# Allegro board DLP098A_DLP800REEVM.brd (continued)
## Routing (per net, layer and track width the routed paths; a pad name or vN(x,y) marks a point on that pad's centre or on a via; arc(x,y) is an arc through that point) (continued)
S_DDA13_P: length 124.5
  TOP w0.191: U8.C16 v1(37.31,41.12)
  03_SIG1 w0.108: v1(37.31,41.12) 37.71,41.12 37.82,41.23 37.82,45.8 36.61,47.01 30.27,47.01 29.98,47.3 29.98,49.21 30.71,49.94 30.71,54.1 31.44,54.83 32.69,54.83 33.8,53.72 38.71,53.72 38.98,53.46 38.98,52.82 38.72,52.57 34.37,52.57 33.05,51.25 33.05,49.16 33.2,49 34.6,49 34.92,49.32 41.79,49.32 42.94,50.47 42.94,54.51 41.63,55.83 41.63,62.71 41.9,62.98 42.54,62.98 42.82,62.7 42.82,58.15 43.61,57.35 46.89,57.35 47.51,57.97 47.51,61.91 48.53,62.94 50.16,62.94 53.12,65.9 53.12,67.19 54.78,68.84 54.78,74.82 55.16,75.2 74.84,75.2 75.1,75.46 75.1,80.05 73.83,81.32 73.83,81.95 73.72,82.06 v1(73.32,82.06)
  BOTTOM w0.108: J500.D17 v1(73.32,82.06)
S_DDA14_N: length 124.4
  TOP w0.191: U8.B15 v1(36.04,42.39)
  05_SIG2 w0.108: v1(75.86,83.33) 75.7,83.17 75.46,83.17 75.24,83.38 75.24,83.63 75.46,83.84 76.23,83.84 76.37,83.7 76.37,68.33 74.71,66.67 73.89,66.67 73.58,66.98 73.58,67.32 74.27,68.01 74.27,68.81 73.81,69.27 73.05,69.27 71.79,68.01 71.79,66.12 67.22,61.56 66.94,61.56 66.66,61.83 66.66,62.19 69.52,65.05 69.52,65.72 69.06,66.18 68.46,66.18 64.91,62.63 64.91,61.63 67.17,59.37 67.17,59.02 66.96,58.81 66.38,58.81 64.13,61.06 63.77,61.06 63.37,60.66 63.37,60.09 65.52,57.94 65.52,57.61 65.24,57.33 64.96,57.33 61.85,60.44 53.99,60.44 51.23,57.68 51.23,57.21 51.73,56.71 52.4,56.71 54.88,59.18 55.34,59.18 55.62,58.91 55.62,58.66 51.25,54.29 49.69,54.29 48.46,53.06 48.46,52.59 47.13,51.25 44.13,51.25 43.79,50.92 39.8,50.92 39.5,50.62 39.5,50.06 39.81,49.75 43.48,49.75 43.63,49.59 43.63,49.31 43.43,49.11 39.7,49.11 39.36,48.78 39.36,47.6 39.92,47.04 39.92,46.25 39.65,45.99 37.84,45.99 36.55,44.71 36.55,42.47 36.45,42.36 36.08,42.36 v1(36.04,42.39)
  BOTTOM w0.108: J500.C19 v1(75.86,83.33)
S_DDA14_P: length 124.5
  TOP w0.191: U8.B16 v1(37.31,42.39)
  05_SIG2 w0.108: v1(74.59,83.33) 75.35,84.09 76.34,84.09 76.62,83.81 76.62,68.22 74.82,66.42 73.78,66.42 73.32,66.87 73.32,67.42 74.02,68.12 74.02,68.7 73.71,69.01 73.15,69.01 72.04,67.91 72.04,66.02 67.33,61.3 66.84,61.3 66.41,61.73 66.41,62.3 69.27,65.15 69.27,65.61 68.95,65.93 68.57,65.93 65.16,62.52 65.16,61.73 67.42,59.47 67.42,58.92 67.06,58.56 66.28,58.56 64.03,60.81 63.87,60.81 63.62,60.56 63.62,60.2 65.77,58.05 65.77,57.51 65.35,57.08 64.85,57.08 61.74,60.19 54.09,60.19 51.48,57.58 51.48,57.32 51.84,56.96 52.3,56.96 54.78,59.44 55.45,59.44 55.87,59.02 55.87,58.55 51.35,54.04 49.8,54.04 48.72,52.96 48.72,52.48 47.23,51 44.23,51 43.9,50.66 39.9,50.66 39.76,50.51 39.76,50.16 39.91,50 43.58,50 43.89,49.7 43.89,49.21 43.53,48.85 39.8,48.85 39.62,48.67 39.62,47.7 40.17,47.15 40.17,46.15 39.76,45.74 37.94,45.74 36.81,44.6 36.81,42.9 v1(37.31,42.39)
  BOTTOM w0.108: J500.C18 v1(74.59,83.33)
S_DDA15_N: length 124.5
  TOP w0.191: U8.D15 v1(36.04,39.85)
  03_SIG1 w0.108: v1(36.04,39.85) 36.04,39.45 35.94,39.34 35.78,39.34 35.55,39.58 35.55,40.25 35.66,40.36 39.04,40.36 39.35,40.67 39.35,44.48 39.54,44.67 41.82,44.67 42.19,45.05 42.19,45.93 41.82,46.31 38.91,46.31 38.75,46.48 38.75,47.06 38.96,47.27 42.67,47.27 43.21,47.81 43.21,48.75 44.82,50.37 44.82,52.87 48.67,56.71 48.67,59.67 54.33,65.33 54.33,66.77 55.19,67.63 55.5,67.63 55.72,67.42 55.72,67.15 55.26,66.69 55.26,64.97 49.45,59.17 49.45,56.41 45.61,52.57 45.61,49.46 45.98,49.08 46.93,49.08 47.4,49.55 47.4,52.62 50.62,55.85 50.62,58.32 57.22,64.91 57.22,67.89 56.3,68.81 56.3,73.38 56.6,73.68 75.42,73.68 76.47,74.74 76.47,75.57 76.62,75.71 v1(77.13,75.71)
  BOTTOM w0.108: J500.H20 v1(77.13,75.71)
S_DDA15_P: length 124.5
  TOP w0.191: U8.E15 v1(36.04,38.58)
  03_SIG1 w0.108: v1(75.86,75.71) 76.22,75.35 76.22,74.84 75.31,73.93 56.49,73.93 56.05,73.49 56.05,68.7 56.96,67.79 56.96,65.02 50.37,58.43 50.37,55.95 47.14,52.72 47.14,49.66 46.82,49.34 46.09,49.34 45.86,49.56 45.86,52.46 49.71,56.31 49.71,59.06 55.52,64.87 55.52,66.59 55.97,67.05 55.97,67.52 55.61,67.89 55.09,67.89 54.08,66.88 54.08,65.44 48.41,59.78 48.41,56.82 44.57,52.97 44.57,50.47 42.96,48.86 42.96,47.91 42.57,47.52 38.85,47.52 38.49,47.16 38.49,46.37 38.81,46.06 41.71,46.06 41.94,45.83 41.94,45.15 41.71,44.92 39.43,44.92 39.1,44.59 39.1,40.77 38.94,40.61 35.55,40.61 35.29,40.35 35.29,39.48 35.68,39.09 35.94,39.09 36.04,38.98 v1(36.04,38.58)
  BOTTOM w0.108: J500.H19 v1(75.86,75.71)
S_DDB00_N: length 149.7
  TOP w0.191: U8.W10 v1(28.42,19.53)
  10_SIG4 w0.108: v1(28.42,19.53) 28.82,19.53 28.93,19.42 28.93,18 28.68,17.75 26.81,17.75 26.39,17.34 26.39,14.23 26.08,13.92 16.82,13.92 14.54,16.19 14.54,43.34 18.32,47.12 18.32,48.89 20.97,51.54 23.47,51.54 26.72,54.79 30.34,54.79 30.8,54.33 31.59,54.33 32.02,54.76 32.02,55.63 32.34,55.94 34.54,55.94 36.18,57.58 57.68,57.58 58.17,58.07 58.17,58.89 57.81,59.26 50.91,59.26 50.69,59.47 50.69,59.78 50.91,60 57.66,60 58.17,60.51 58.17,62.19 58.99,63.01 60.29,63.01 61.08,62.22 62.57,62.22 63.04,62.69 63.04,63.44 60.4,66.07 59.32,66.07 53.76,71.62 53.76,77.3 53.96,77.49 57.05,77.49 57.32,77.76 57.32,78.32 57.45,78.44 57.89,78.44 v1(58.08,78.25)
  BOTTOM w0.108: J500.F05 v1(58.08,78.25)
S_DDB00_P: length 149.7
  TOP w0.191: U8.W11 v1(29.69,19.53)
  10_SIG4 w0.108: v1(56.81,78.25) 57.07,77.99 57.07,77.86 56.95,77.74 53.85,77.74 53.51,77.4 53.51,71.52 59.21,65.81 60.3,65.81 62.78,63.33 62.78,62.79 62.46,62.47 61.19,62.47 60.4,63.26 58.89,63.26 57.92,62.29 57.92,60.62 57.56,60.25 50.8,60.25 50.44,59.89 50.44,59.37 50.8,59 57.7,59 57.92,58.78 57.92,58.17 57.58,57.83 36.07,57.83 34.44,56.19 32.23,56.19 31.77,55.73 31.77,54.87 31.48,54.58 30.91,54.58 30.45,55.05 26.61,55.05 23.36,51.8 20.87,51.8 18.07,49 18.07,47.23 14.29,43.45 14.29,16.08 16.71,13.66 26.18,13.66 26.64,14.12 26.64,17.23 26.91,17.5 28.79,17.5 29.19,17.9 29.19,19.42 29.29,19.53 v1(29.69,19.53)
  BOTTOM w0.108: J500.F04 v1(56.81,78.25)
S_DDB01_N: length 149.8
  TOP w0.191: U8.Z3 v1(19.53,15.72)
  10_SIG4 w0.108: v1(55.54,80.79) 55.49,80.74 55.05,80.74 54.95,80.85 54.95,81.11 55.14,81.3 58.32,81.3 58.59,81.03 58.59,69.38 60.21,67.76 63.53,67.76 63.86,67.43 63.86,65.85 64.21,65.5 64.72,65.5 65.04,65.82 65.04,67.58 65.16,67.7 65.59,67.7 65.7,67.59 65.7,62.27 63.81,60.38 60.78,60.38 60.09,59.69 60.09,57.86 61.16,56.78 68.76,56.78 70.69,58.7 71.21,58.7 71.38,58.53 71.38,58.12 69.12,55.86 49.86,55.86 48.03,54.03 37.94,54.03 34.01,50.1 28.69,50.1 27.99,50.79 25.38,50.79 24.43,49.85 23.58,49.85 22.96,49.23 21.32,49.23 20.53,48.44 20.53,47.19 16.1,42.76 16.1,16.7 16.57,16.23 19.43,16.23 19.53,16.12 v1(19.53,15.72)
  BOTTOM w0.108: J500.E03 v1(55.54,80.79)
S_DDB01_P: length 149.8
  TOP w0.191: U8.Y3 v1(19.53,16.99)
  10_SIG4 w0.108: v1(54.27,80.79) 55.03,81.55 58.42,81.55 58.84,81.14 58.84,69.48 60.31,68.01 63.64,68.01 64.11,67.54 64.11,65.96 64.31,65.76 64.61,65.76 64.79,65.93 64.79,67.68 65.06,67.96 65.69,67.96 65.95,67.7 65.95,62.17 63.91,60.13 60.88,60.13 60.34,59.59 60.34,57.96 61.27,57.03 68.66,57.03 70.58,58.96 71.31,58.96 71.64,58.63 71.64,58.01 69.23,55.6 49.96,55.6 48.14,53.78 38.04,53.78 34.11,49.85 28.58,49.85 27.89,50.54 25.48,50.54 24.54,49.6 23.69,49.6 23.06,48.97 21.42,48.97 20.79,48.34 20.79,47.09 16.35,42.65 16.35,16.81 16.67,16.48 19.43,16.48 19.53,16.59 v1(19.53,16.99)
  BOTTOM w0.108: J500.E02 v1(54.27,80.79)
S_DDB02_N: length 149.8
  TOP w0.191: U8.W4 v1(20.8,19.53)
  10_SIG4 w0.108: v1(20.8,19.53) 20.8,19.13 20.7,19.02 19.21,19.02 19.03,19.2 19.03,38.86 19.26,39.09 19.9,39.09 20.29,39.49 20.29,44.1 23.06,46.87 42.42,46.87 43.27,47.72 43.27,48.66 42.81,49.12 39.62,49.12 39.08,49.66 39.08,50.45 39.64,51.01 57.14,51.01 59.89,53.75 69.98,53.75 75.07,58.84 77.69,58.84 78.09,59.24 78.09,60.84 77.62,61.31 68.96,61.31 67.78,62.49 67.78,64.62 68.86,65.69 77.52,65.69 77.9,66.07 77.9,66.92 77.55,67.26 69.27,67.26 64.3,72.23 61.61,72.23 61.23,72.61 61.23,73 61.4,73.17 v1(61.89,73.17)
  BOTTOM w0.108: J500.K08 v1(61.89,73.17)
S_DDB02_P: length 149.8
  TOP w0.191: U8.X4 v1(20.8,18.26)
  10_SIG4 w0.108: v1(20.8,18.26) 20.8,18.66 20.7,18.77 19.1,18.77 18.78,19.1 18.78,38.96 19.16,39.35 19.8,39.35 20.04,39.59 20.04,44.21 22.96,47.12 42.32,47.12 43.02,47.83 43.02,48.55 42.7,48.87 39.52,48.87 38.83,49.56 38.83,50.55 39.54,51.26 57.03,51.26 59.78,54.01 69.87,54.01 74.96,59.1 77.59,59.1 77.84,59.35 77.84,60.73 77.51,61.06 68.85,61.06 67.53,62.39 67.53,64.72 68.75,65.95 77.41,65.95 77.64,66.18 77.64,66.81 77.45,67.01 69.16,67.01 64.19,71.98 61.5,71.98 60.98,72.5 60.98,72.82 v1(60.62,73.17)
  BOTTOM w0.108: J500.K07 v1(60.62,73.17)
S_DDB03_N: length 149.7
  TOP w0.191: U8.Y7 v1(24.61,16.99)
  08_SIG3 w0.108: v1(24.61,16.99) 24.86,17.24 24.86,17.4 24.76,17.5 15.72,17.5 13.95,19.27 13.95,41.96 18.32,46.32 29.48,46.32 30.06,46.91 30.06,48.87 31.26,50.07 44.14,50.07 44.61,50.54 44.61,52.64 44.14,53.11 32.61,53.11 32.24,53.48 32.24,54.2 32.62,54.58 46.44,54.58 48.16,56.3 55.51,56.3 58.93,59.72 58.93,63.91 57.94,64.89 56.13,64.89 52.7,68.32 52.7,71.48 51.63,72.55 51.63,75.62 52.48,76.47 53.22,76.47 53.51,76.76 53.51,77.3 53.96,77.75 59.73,77.75 60.11,77.37 60.11,74.57 60.23,74.44 v1(60.62,74.44)
  BOTTOM w0.108: J500.J07 v1(60.62,74.44)
S_DDB03_P: length 149.7
  TOP w0.191: U8.Y8 v1(25.88,16.99)
  08_SIG3 w0.108: v1(25.88,16.99) 25.69,16.8 25.3,16.8 25.12,16.98 25.12,17.5 24.86,17.76 15.83,17.76 14.21,19.37 14.21,41.86 18.42,46.07 29.59,46.07 30.32,46.8 30.32,48.77 31.37,49.82 44.25,49.82 44.87,50.44 44.87,52.74 44.24,53.37 32.71,53.37 32.5,53.58 32.5,54.1 32.73,54.33 46.54,54.33 48.26,56.05 55.61,56.05 59.18,59.62 59.18,64.01 58.04,65.15 56.23,65.15 52.95,68.43 52.95,71.59 51.88,72.66 51.88,75.52 52.59,76.22 53.33,76.22 53.76,76.65 53.76,77.19 54.06,77.49 59.63,77.49 59.85,77.27 59.85,74.55 59.75,74.44 v1(59.35,74.44)
  BOTTOM w0.108: J500.J06 v1(59.35,74.44)
S_DDB04_N: length 149.7
  TOP w0.191: U8.X8 v1(25.88,18.26)
  10_SIG4 w0.108: v1(61.89,78.25) 61.49,78.25 61.39,78.15 61.39,77.99 61.63,77.74 67.36,77.74 67.73,77.37 67.73,72.68 72.21,68.2 78.06,68.2 78.84,67.42 78.84,65.51 78.11,64.78 69.87,64.78 69.11,64.02 69.11,62.98 69.85,62.24 78.82,62.24 79.47,61.59 79.47,58.6 78.83,57.96 75.61,57.96 70.51,52.86 60.27,52.86 57.53,50.12 47.24,50.12 43.12,45.99 23.55,45.99 21.57,44.02 21.57,38.18 21.21,37.82 20.6,37.82 20.3,37.52 20.3,20.57 20.57,20.29 21.28,20.29 21.57,20.01 21.57,19.21 21.76,19.02 24.98,19.02 25.38,18.63 25.38,18.37 25.48,18.26 v1(25.88,18.26)
  BOTTOM w0.108: J500.F08 v1(61.89,78.25)
S_DDB04_P: length 149.8
  TOP w0.191: U8.X7 v1(24.61,18.26)
  10_SIG4 w0.108: v1(24.61,18.26) 25.01,18.26 25.12,18.37 25.12,18.52 24.88,18.77 21.65,18.77 21.31,19.11 21.31,19.9 21.18,20.04 20.47,20.04 20.05,20.46 20.05,37.62 20.5,38.08 21.11,38.08 21.32,38.28 21.32,44.12 23.44,46.25 43.02,46.25 47.14,50.37 57.42,50.37 60.16,53.11 70.4,53.11 75.51,58.22 78.73,58.22 79.21,58.7 79.21,61.49 78.72,61.98 69.74,61.98 68.85,62.88 68.85,64.12 69.76,65.04 78.01,65.04 78.59,65.62 78.59,67.32 77.96,67.95 72.1,67.95 67.48,72.57 67.48,77.27 67.26,77.49 61.52,77.49 61.13,77.88 61.13,78.14 61.02,78.25 v1(60.62,78.25)
  BOTTOM w0.108: J500.F07 v1(60.62,78.25)
S_DDB05_N: length 149.8
  TOP w0.191: U8.Y6 v1(23.34,16.99)
  10_SIG4 w0.108: v1(60.62,80.79) 60.54,80.71 60.22,80.71 60.03,80.9 60.03,81.11 60.21,81.29 60.94,81.29 61.13,81.1 61.13,79.98 59.85,78.7 59.85,71.75 62.92,68.68 66.07,68.68 66.64,68.11 66.64,60.92 67.12,60.44 68.24,60.44 68.5,60.18 68.5,59.74 68.22,59.46 62.12,59.46 61.77,59.12 61.77,58.3 62.21,57.86 68.47,57.86 70.78,60.18 73.25,60.18 73.76,59.66 73.76,59.26 69.43,54.92 50.32,54.92 48.39,52.99 38.42,52.99 37.74,52.31 37.74,49.76 37.2,49.22 36.79,49.22 36.41,49.6 35.2,49.6 34.82,49.22 27.37,49.22 26.33,48.18 22.78,48.18 17.5,42.9 17.5,17.91 17.91,17.5 23.24,17.5 23.34,17.39 v1(23.34,16.99)
  BOTTOM w0.108: J500.E07 v1(60.62,80.79)
S_DDB05_P: length 149.8
  TOP w0.191: U8.X6 v1(23.34,18.26)
  10_SIG4 w0.108: v1(23.34,18.26) 23.34,17.86 23.24,17.75 18.01,17.75 17.75,18.01 17.75,42.79 22.88,47.92 26.44,47.92 27.48,48.96 34.92,48.96 35.31,49.35 36.3,49.35 36.68,48.96 37.3,48.96 38,49.66 38,52.2 38.53,52.73 48.5,52.73 50.43,54.66 69.53,54.66 74.02,59.15 74.02,59.77 73.35,60.43 70.68,60.43 68.36,58.11 62.31,58.11 62.02,58.4 62.02,59.01 62.22,59.21 68.33,59.21 68.75,59.63 68.75,60.28 68.34,60.7 67.23,60.7 66.9,61.03 66.9,68.21 66.18,68.93 63.03,68.93 60.11,71.85 60.11,78.6 61.38,79.87 61.38,81.2 61.04,81.54 60.1,81.54 v1(59.35,80.79)
  BOTTOM w0.108: J500.E06 v1(59.35,80.79)
S_DDB06_N: length 149.8
  TOP w0.191: U8.X3 v1(19.53,18.26)
  08_SIG3 w0.108: v1(65.7,73.17) 64.94,73.94 59.06,73.94 58.84,74.16 58.84,76.08 58.45,76.47 53.96,76.47 53.5,76.02 53.5,75.5 53.21,75.2 52.6,75.2 52.24,74.84 52.24,72.85 53.58,71.51 53.58,69.35 55.3,67.62 57.81,67.62 60.66,64.78 60.66,59.59 56.4,55.33 48.48,55.33 45.57,52.42 45.57,49.55 45.17,49.16 32.67,49.16 32.12,48.61 32.12,47.17 32.65,46.65 45.67,46.65 45.98,46.33 45.98,45.78 45.63,45.43 18.72,45.43 14.94,41.65 14.94,20.08 16.26,18.77 19.43,18.77 19.53,18.66 v1(19.53,18.26)
  BOTTOM w0.108: J500.K11 v1(65.7,73.17)
S_DDB06_P: length 149.8
  TOP w0.191: U8.W3 v1(19.53,19.53)
  08_SIG3 w0.108: v1(64.43,73.17) 64.43,72.78 64.54,72.67 64.88,72.67 65,72.78 65,73.52 64.83,73.68 58.96,73.68 58.59,74.05 58.59,75.98 58.34,76.22 54.06,76.22 53.76,75.92 53.76,75.39 53.32,74.95 52.71,74.95 52.49,74.73 52.49,72.96 53.83,71.62 53.83,69.45 55.41,67.88 57.92,67.88 60.91,64.88 60.91,59.49 56.5,55.07 48.58,55.07 45.82,52.31 45.82,49.45 45.28,48.91 32.77,48.91 32.37,48.51 32.37,47.28 32.75,46.9 45.77,46.9 46.24,46.44 46.24,45.67 45.74,45.18 18.82,45.18 15.2,41.55 15.2,20.19 16.36,19.02 19.43,19.02 19.53,19.13 v1(19.53,19.53)
  BOTTOM w0.108: J500.K10 v1(64.43,73.17)
S_DDB07_N: length 149.8
  TOP w0.191: U8.Z8 v1(25.88,15.72)
  08_SIG3 w0.108: v1(64.43,74.44) 64.03,74.44 63.92,74.55 63.92,78.6 63.33,79.19 54.05,79.19 53.51,78.64 53.51,78.04 53.21,77.75 52.36,77.75 50.96,76.36 50.96,72.32 51.78,71.5 51.78,67.79 55.87,63.7 56.81,63.7 57.94,62.57 57.94,60.31 55.25,57.62 38.79,57.62 38.44,57.26 38.44,56.74 38.76,56.42 46.13,56.42 46.4,56.16 46.4,55.8 46.15,55.55 32.18,55.55 31.16,54.54 31.16,53.88 30.73,53.45 30.73,51.1 28.78,49.15 26.98,49.15 25.1,47.27 17.93,47.27 12.78,42.12 12.78,18.86 15.41,16.23 26.02,16.23 26.14,16.12 26.14,15.98 v1(25.88,15.72)
  BOTTOM w0.108: J500.J10 v1(64.43,74.44)
S_DDB07_P: length 149.8
  TOP w0.191: U8.Z9 v1(27.15,15.72)
  08_SIG3 w0.108: v1(63.16,74.44) 63.56,74.44 63.67,74.55 63.67,78.49 63.23,78.93 54.16,78.93 53.76,78.54 53.76,77.94 53.32,77.49 52.46,77.49 51.22,76.25 51.22,72.42 52.03,71.61 52.03,67.9 55.97,63.96 56.92,63.96 58.2,62.68 58.2,60.21 55.35,57.36 38.9,57.36 38.69,57.15 38.69,56.85 38.86,56.68 46.24,56.68 46.65,56.26 46.65,55.7 46.26,55.3 32.28,55.3 31.42,54.43 31.42,53.77 30.99,53.35 30.99,51 28.89,48.9 27.09,48.9 25.2,47.01 18.03,47.01 13.04,42.02 13.04,18.96 15.52,16.48 26.13,16.48 26.39,16.22 26.39,15.7 26.58,15.51 26.94,15.51 v1(27.15,15.72)
  BOTTOM w0.108: J500.J09 v1(63.16,74.44)
S_DDB08_N: length 149.8
  TOP w0.191: U8.Z6 v1(23.34,15.72)
  08_SIG3 w0.108: v1(23.34,15.72) 22.94,15.72 22.84,15.61 22.84,15.35 22.44,14.96 15.22,14.96 11.89,18.29 11.89,42.51 18.5,49.12 23.05,49.12 30.35,56.42 37.39,56.42 37.52,56.55 37.52,56.99 37.32,57.19 29.98,57.19 27.9,55.11 27.31,55.11 26.99,55.43 26.99,55.99 29.56,58.56 54.29,58.56 55.09,59.36 55.09,61.96 50.86,66.19 50.86,71.24 50.37,71.73 50.37,77.09 53.28,80 63.96,80 v1(65.7,78.25)
  BOTTOM w0.108: J500.F11 v1(65.7,78.25)
S_DDB08_P: length 149.8
  TOP w0.191: U8.Z5 v1(22.07,15.72)
  08_SIG3 w0.108: v1(22.07,15.72) 22.47,15.72 22.58,15.61 22.58,15.46 22.34,15.21 15.33,15.21 12.14,18.39 12.14,42.4 18.61,48.87 23.15,48.87 30.45,56.17 37.49,56.17 37.77,56.45 37.77,57.09 37.42,57.44 29.88,57.44 27.8,55.36 27.41,55.36 27.24,55.53 27.24,55.88 29.67,58.31 54.4,58.31 55.35,59.26 55.35,62.06 51.12,66.29 51.12,71.34 50.63,71.83 50.63,76.98 53.39,79.74 63.85,79.74 65.09,78.51 65.09,77.71 64.96,77.59 64.57,77.59 64.43,77.73 v1(64.43,78.25)
  BOTTOM w0.108: J500.F10 v1(64.43,78.25)
S_DDB09_N: length 149.7
  TOP w0.191: U8.Y10 v1(28.42,16.99)
  10_SIG4 w0.108: v1(64.43,80.79) 63.99,80.79 63.72,80.53 63.72,80.23 63.47,79.97 62.73,79.97 62.39,80.31 62.39,82.37 62.19,82.57 54,82.57 53.76,82.33 53.76,79.97 52.42,78.64 52.42,69.33 53.93,67.82 56.09,67.82 57.7,66.21 57.7,63.6 55.31,61.21 44.67,61.21 44.36,60.9 44.36,60.41 44.65,60.11 49.28,60.11 49.67,59.72 49.67,59.04 49.31,58.68 35.1,58.68 33.54,57.12 27.5,57.12 22.94,52.56 20.73,52.56 17.42,49.26 17.42,47.56 13.63,43.76 13.63,15.76 16.45,12.94 26.44,12.94 27.67,14.16 27.67,16.09 28.06,16.48 28.32,16.48 28.42,16.59 v1(28.42,16.99)
  BOTTOM w0.108: J500.E10 v1(64.43,80.79)
S_DDB09_P: length 149.7
  TOP w0.191: U8.Z10 v1(28.42,15.72)
  10_SIG4 w0.108: v1(63.16,80.79) 63.47,80.48 63.47,80.33 63.36,80.22 62.84,80.22 62.65,80.41 62.65,82.48 62.3,82.83 53.9,82.83 53.5,82.43 53.5,80.08 52.17,78.74 52.17,69.22 53.82,67.57 55.98,67.57 57.45,66.1 57.45,63.71 55.21,61.47 44.56,61.47 44.1,61.01 44.1,60.3 44.55,59.86 49.18,59.86 49.42,59.62 49.42,59.14 49.21,58.93 34.99,58.93 33.43,57.37 27.4,57.37 22.84,52.81 20.62,52.81 17.17,49.36 17.17,47.67 13.37,43.87 13.37,15.66 16.35,12.68 26.54,12.68 27.92,14.06 27.92,15.99 28.16,16.23 28.32,16.23 28.42,16.12 v1(28.42,15.72)
  BOTTOM w0.108: J500.E09 v1(63.16,80.79)
S_DDB10_N: length 149.7
  TOP w0.191: U8.AA9 v1(27.15,14.45)
  08_SIG3 w0.108: v1(69.51,73.17) 69.26,73.42 68.97,73.42 68.8,73.25 68.8,72.97 68.94,72.83 68.94,72.47 68.66,72.18 66.76,72.18 66.2,72.74 66.2,81.05 65.95,81.3 51.25,81.3 50.05,80.1 50.05,62.91 51.23,61.72 53.48,61.72 54.06,61.14 54.06,59.88 53.48,59.3 29.41,59.3 25.97,55.86 25.97,54.3 21.95,50.28 18.75,50.28 11.16,42.68 11.16,17.91 15.27,13.8 27.4,13.8 27.66,14.06 27.66,14.34 27.55,14.45 v1(27.15,14.45)
  BOTTOM w0.108: J500.K14 v1(69.51,73.17)
S_DDB10_P: length 149.7
  TOP w0.191: U8.AA10 v1(28.42,14.45)
  08_SIG3 w0.108: v1(68.24,73.17) 68.69,72.72 68.69,72.57 68.55,72.44 66.87,72.44 66.46,72.84 66.46,81.15 66.05,81.56 51.14,81.56 49.79,80.21 49.79,62.8 51.13,61.47 53.38,61.47 53.8,61.04 53.8,59.98 53.37,59.55 29.31,59.55 25.72,55.97 25.72,54.41 21.85,50.53 18.65,50.53 10.91,42.79 10.91,17.81 15.17,13.55 27.51,13.55 27.92,13.95 27.92,14.34 28.02,14.45 v1(28.42,14.45)
  BOTTOM w0.108: J500.K13 v1(68.24,73.17)
S_DDB11_N: length 149.7
  TOP w0.191: U8.Y13 v1(33.5,16.99)
  08_SIG3 w0.108: v1(68.24,74.44) 67.73,74.95 67.73,82.38 67.28,82.83 51.1,82.83 48.91,80.64 48.91,68.43 48.5,68.02 48.5,66.03 43.11,60.63 29.03,60.63 25.31,56.91 24.22,56.91 20.05,52.74 16.76,52.74 14.3,50.28 14.3,47.48 9.96,43.14 9.96,17.41 14.73,12.65 29.24,12.65 31.72,15.14 31.72,16.14 33.27,17.68 33.8,17.68 34.01,17.47 34.01,17.1 33.9,16.99 v1(33.5,16.99)
  BOTTOM w0.108: J500.J13 v1(68.24,74.44)
S_DDB11_P: length 149.7
  TOP w0.191: U8.Y14 v1(34.77,16.99)
  08_SIG3 w0.108: v1(66.97,74.44) 66.97,74.42 67.24,74.15 67.47,74.15 67.63,74.31 67.63,74.7 67.48,74.85 67.48,82.27 67.18,82.57 51.2,82.57 49.16,80.53 49.16,68.32 48.76,67.91 48.76,65.93 43.21,60.38 29.13,60.38 25.41,56.66 24.33,56.66 20.15,52.48 16.87,52.48 14.55,50.17 14.55,47.38 10.21,43.04 10.21,17.52 14.83,12.9 29.13,12.9 31.47,15.24 31.47,16.24 33.16,17.94 33.91,17.94 34.27,17.58 34.27,17.1 34.37,16.99 v1(34.77,16.99)
  BOTTOM w0.108: J500.J12 v1(66.97,74.44)
S_DDB12_N: length 149.8
  TOP w0.191: U8.Z12 v1(30.96,15.72)
  10_SIG4 w0.108: v1(30.96,15.72) 31.36,15.72 31.47,15.83 31.47,16.11 31.35,16.23 29.48,16.23 29.19,15.94 29.19,14 26.97,11.78 15.93,11.78 12.48,15.23 12.48,44.32 15.89,47.73 15.89,51.44 17.32,52.88 19.42,52.88 22.33,55.78 24.42,55.78 27.17,58.53 33.14,58.53 34.51,59.9 41.08,59.9 43.68,62.51 50.83,62.51 53.16,64.84 53.16,66.42 51.19,68.4 51.19,76.72 49.81,78.1 49.81,81.26 52.65,84.09 64.76,84.09 65.19,83.66 65.19,79.95 65.77,79.38 68.38,79.38 v1(69.51,78.25)
  BOTTOM w0.108: J500.F14 v1(69.51,78.25)
S_DDB12_P: length 149.8
  TOP w0.191: U8.Z13 v1(32.23,15.72)
  10_SIG4 w0.108: v1(32.23,15.72) 31.83,15.72 31.73,15.83 31.73,16.22 31.46,16.48 29.37,16.48 28.93,16.05 28.93,14.1 26.87,12.04 16.03,12.04 12.74,15.33 12.74,44.21 16.15,47.62 16.15,51.34 17.43,52.62 19.53,52.62 22.43,55.52 24.52,55.52 27.27,58.28 33.24,58.28 34.62,59.65 41.18,59.65 43.79,62.25 50.93,62.25 53.41,64.73 53.41,66.53 51.44,68.5 51.44,76.82 50.06,78.2 50.06,81.15 52.75,83.84 64.65,83.84 64.94,83.55 64.94,79.85 65.66,79.13 68.28,79.13 68.9,78.51 68.9,78.08 68.79,77.97 68.52,77.97 v1(68.24,78.25)
  BOTTOM w0.108: J500.F13 v1(68.24,78.25)
S_DDB13_N: length 149.8
  TOP w0.191: U8.Y17 v1(38.58,16.99)
  10_SIG4 w0.108: v1(38.58,16.99) 38.18,16.99 38.08,16.88 38.08,15.41 37.63,14.96 36.61,14.96 32.56,10.91 15.57,10.91 11.61,14.87 11.61,44.84 14.24,47.47 14.24,51.03 17.96,54.75 19.73,54.75 21.75,56.78 23.91,56.78 28.27,61.14 40.84,61.14 48.93,69.22 48.93,81.63 52.66,85.36 66.02,85.36 67.73,83.66 67.73,81.3 v1(68.24,80.79)
  BOTTOM w0.108: J500.E13 v1(68.24,80.79)
S_DDB13_P: length 149.8
  TOP w0.191: U8.Y16 v1(37.31,16.99)
  10_SIG4 w0.108: v1(37.31,16.99) 37.71,16.99 37.82,16.88 37.82,15.51 37.53,15.21 36.5,15.21 32.45,11.17 15.67,11.17 11.86,14.97 11.86,44.73 14.5,47.37 14.5,50.93 18.07,54.5 19.83,54.5 21.86,56.53 24.02,56.53 28.37,60.88 40.95,60.88 49.18,69.12 49.18,81.53 52.77,85.11 65.92,85.11 67.48,83.55 67.48,80.26 67.33,80.12 67.04,80.12 66.8,80.35 66.8,80.62 v1(66.97,80.79)
  BOTTOM w0.108: J500.E12 v1(66.97,80.79)
S_DDB14_N: length 149.8
  TOP w0.191: U8.Z15 v1(36.04,15.72)
  08_SIG3 w0.108: v1(36.04,15.72) 36.44,15.72 36.55,15.61 36.55,15.34 36.34,15.13 35.66,15.13 35.54,15.25 35.54,19.96 35.2,20.29 16.78,20.29 16.18,20.89 16.18,41.25 19.23,44.3 46.11,44.3 47.95,46.14 47.95,52.29 49.76,54.1 57.75,54.1 61.87,58.23 61.87,65.63 57.99,69.51 56.35,69.51 54.97,70.89 54.97,71.73 53.76,72.95 53.76,74.64 54.06,74.95 57.08,74.95 57.32,74.71 57.32,72.77 57.89,72.21 63.87,72.21 64.56,71.51 70.78,71.51 71.67,72.4 71.67,73.91 71.37,74.21 71.37,74.58 71.5,74.71 71.79,74.71 v1(72.05,74.44)
  BOTTOM w0.108: J500.J16 v1(72.05,74.44)
S_DDB14_P: length 149.8
  TOP w0.191: U8.Z16 v1(37.31,15.72)
  08_SIG3 w0.108: v1(37.31,15.72) 36.91,15.72 36.81,15.61 36.81,15.23 36.45,14.87 35.55,14.87 35.28,15.14 35.28,19.85 35.1,20.04 16.68,20.04 15.93,20.78 15.93,41.36 19.13,44.56 46.01,44.56 47.7,46.25 47.7,52.4 49.65,54.35 57.64,54.35 61.62,58.33 61.62,65.53 57.89,69.26 56.25,69.26 54.72,70.79 54.72,71.63 53.5,72.84 53.5,74.75 53.96,75.2 57.18,75.2 57.57,74.81 57.57,72.88 57.99,72.46 63.97,72.46 64.67,71.76 70.67,71.76 71.42,72.51 71.42,73.8 v1(70.78,74.44)
  BOTTOM w0.108: J500.J15 v1(70.78,74.44)
S_DDB15_N: length 149.7
  TOP w0.191: U8.X15 v1(36.04,18.26)
  10_SIG4 w0.108: v1(36.04,18.26) 36.04,18.66 35.94,18.77 35.68,18.77 35.3,19.15 35.3,20.1 34.87,20.53 23.12,20.53 22.02,21.63 22.02,36.12 23.86,37.96 23.86,44.03 24.29,44.47 47.38,44.47 50.29,47.38 57.03,47.38 60.87,51.21 71.28,51.21 76.36,56.29 81.06,56.29 82.14,57.36 82.14,71.19 80.17,73.15 80.17,78.69 79.83,79.04 78.58,79.04 78.15,78.61 78.15,73.88 76.47,72.2 72.93,72.2 71.29,73.84 71.29,78.64 71.68,79.03 72.54,79.03 v1(73.32,78.25)
  BOTTOM w0.108: J500.F17 v1(73.32,78.25)
S_DDB15_P: length 149.7
  TOP w0.191: U8.W15 v1(36.04,19.53)
  10_SIG4 w0.108: v1(72.05,78.25) 72.05,77.9 72.18,77.77 72.53,77.77 72.68,77.92 72.68,78.54 72.43,78.78 71.79,78.78 71.54,78.54 71.54,73.94 73.04,72.45 76.36,72.45 77.9,73.99 77.9,78.71 78.48,79.29 79.93,79.29 80.43,78.8 80.43,73.26 82.39,71.3 82.39,57.26 81.17,56.04 76.46,56.04 71.39,50.96 60.97,50.96 57.13,47.12 50.4,47.12 47.49,44.22 24.4,44.22 24.11,43.93 24.11,37.85 22.27,36.01 22.27,21.73 23.23,20.78 34.98,20.78 35.55,20.21 35.55,19.26 35.78,19.02 35.94,19.02 36.04,19.13 v1(36.04,19.53)
  BOTTOM w0.108: J500.F16 v1(72.05,78.25)
S_SCTRLA_N: length 124.4
  TOP w0.191: U8.E4 v1(20.8,38.58)
  05_SIG2 w0.108: v1(75.86,76.98) 75.46,76.98 75.35,76.87 75.35,72.59 72.44,69.68 70.37,67.61 68.95,67.61 63.16,61.83 61.06,61.83 60.4,61.17 53.84,61.17 52.3,59.63 51.24,59.63 45.87,54.26 45.87,53.96 45.98,53.85 46.5,53.85 49.12,56.48 49.67,56.48 50.06,56.09 50.06,55.54 47.19,52.66 45.64,52.66 45.47,52.49 40.93,52.49 40.63,52.79 40.63,53.3 40.96,53.63 43.86,53.63 44.02,53.79 44.02,54.09 43.86,54.25 40.66,54.25 39.85,53.44 39.85,51.87 38,50.03 38,47.05 35.54,44.59 35.54,39.57 35.76,39.34 45.42,39.34 45.7,39.07 45.7,37.71 45.08,37.1 24.29,37.1 23.86,37.53 23.86,38.9 23.66,39.09 20.91,39.09 20.8,38.98 v1(20.8,38.58)
  BOTTOM w0.108: J500.G19 v1(75.86,76.98)
S_SCTRLA_P: length 124.4
  TOP w0.191: U8.D4 v1(20.8,39.85)
  05_SIG2 w0.108: v1(74.59,76.98) 74.99,76.98 75.1,76.87 75.1,72.7 70.27,67.87 68.84,67.87 63.06,62.09 60.96,62.09 60.3,61.43 53.74,61.43 52.19,59.89 51.14,59.89 45.62,54.37 45.62,53.86 45.87,53.6 46.6,53.6 49.23,56.23 49.57,56.23 49.81,55.98 49.81,55.65 47.08,52.92 45.54,52.92 45.37,52.75 41.03,52.75 40.89,52.89 40.89,53.2 41.07,53.37 43.97,53.37 44.27,53.68 44.27,54.2 43.96,54.51 40.55,54.51 39.59,53.55 39.59,51.98 37.75,50.13 37.75,47.16 35.29,44.69 35.29,39.46 35.66,39.09 45.31,39.09 45.44,38.96 45.44,37.81 44.98,37.35 24.4,37.35 24.11,37.64 24.11,39 23.77,39.34 20.66,39.34 20.56,39.45 20.56,39.73 20.68,39.85 v1(20.8,39.85)
  BOTTOM w0.108: J500.G18 v1(74.59,76.98)
S_SCTRLB_N: length 149.7
  TOP w0.191: U8.W5 v1(22.07,19.53)
  10_SIG4 w0.108: v1(22.07,19.53) 22.47,19.53 22.58,19.64 22.58,19.91 21.31,21.18 21.31,36.54 22.58,37.81 22.58,44.11 23.82,45.35 46.83,45.35 47.54,46.06 47.54,48.39 48.42,49.28 57.67,49.28 60.56,52.17 70.87,52.17 76.03,57.33 80.69,57.33 81.12,57.77 81.12,62.39 80.61,62.9 70.21,62.9 69.84,63.27 69.84,63.79 70.2,64.15 80.69,64.15 81.07,64.53 81.07,68.33 80.52,68.87 73.18,68.87 70.02,72.04 70.02,81.1 70.48,81.55 71.29,81.55 v1(72.05,80.79)
  BOTTOM w0.108: J500.E16 v1(72.05,80.79)
S_SCTRLB_P: length 149.7
  TOP w0.191: U8.W6 v1(23.34,19.53)
  10_SIG4 w0.108: v1(70.78,80.79) 71.08,80.49 71.29,80.49 71.44,80.64 71.44,81.05 71.18,81.3 70.58,81.3 70.27,80.99 70.27,72.14 73.29,69.13 80.62,69.13 81.32,68.43 81.32,64.42 80.8,63.9 70.31,63.9 70.09,63.69 70.09,63.38 70.32,63.16 80.72,63.16 81.38,62.49 81.38,57.66 80.79,57.07 76.13,57.07 70.98,51.92 60.66,51.92 57.77,49.02 48.53,49.02 47.8,48.29 47.8,45.95 46.94,45.1 23.93,45.1 22.83,44 22.83,37.7 21.57,36.44 21.57,21.28 22.84,20.01 22.84,19.64 22.94,19.53 v1(23.34,19.53)
  BOTTOM w0.108: J500.E15 v1(70.78,80.79)
SCP_CLK: length 177.3
  TOP w0.191: U7.56 78.22,25.6 77.35,26.47 77.35,48.72 74.98,51.09 59.71,51.09 55.56,55.24 34.39,55.24 31.57,52.43 v1(29.12,52.43) 29.61,52.92 31.24,52.92 34.83,56.5 56.03,56.5 61.25,61.73 61.25,86.19 61.57,86.51 92.67,86.51 93,86.17 93,85.24 v1(93.64,84.6)
  BOTTOM w0.191: J500.B32 v1(93.64,84.6) ; R27.2 29.82,51.72 v1(29.12,52.43) 28.41,51.72 U9.5
SCP_CLK_1V8: length 37.2
  TOP w0.191: U8.U2 v1(18.26,22.07)
  BOTTOM w0.191: v1(18.26,22.07) 17.63,22.71 15.19,22.71 13.06,24.84 13.06,44.22 16.39,47.55 16.39,48.57 17.8,49.97 17.8,50.27 19.5,51.97 R23.1
SCP_DAD_CSZ: length 69.4
  TOP w0.191: U7.58 77.46,24.6 75.2,26.87 v1(75.2,47.8) ; v1(83.18,55.22) 83.18,68.08 R3.2 84.11,69.08 84.11,83.97 v1(83.48,84.6)
  BOTTOM w0.191: v1(83.18,55.22) 82.62,55.22 v1(75.2,47.8) ; J500.B24 v1(83.48,84.6)
SCP_DMD_CSZ: length 98.8
  TOP w0.191: v1(59.35,83.33) 58.71,83.97 58.71,86.21 58.39,86.53 52.74,86.53 52.34,86.13 R4.2 49.76,66.47 49.76,63.93 45.96,60.13 32.36,60.13 25.68,53.44 25.68,50.02 v1(27.55,48.15) 26.07,46.67 10.78,46.67 9.4,48.05 9.4,51.77 v1(9.88,52.25)
  BOTTOM w0.191: v1(27.55,48.15) 28.27,48.87 28.27,49.18 ; J500.C06 v1(59.35,83.33) ; U10.5 9.9,52.23 v1(9.88,52.25) ; 28.27,49.18 27.38,49.18 26.77,49.79 U9.7 ; 28.27,49.18 R29.2
SCP_DMD_CSZ_1V8: length 35.1
  TOP w0.191: U8.U4 v1(20.8,22.07)
  BOTTOM w0.191: R25.1 18.06,47.8 18.06,46.84 14.84,43.61 14.84,26.21 15.8,25.25 19.89,25.25 20.17,24.97 20.17,22.71 v1(20.8,22.07)
SCP_MISO: length 150.8
  TOP w0.191: v1(98.72,84.6) 98.08,83.97 98.08,72.85 97.08,71.85 92.19,71.85 v1(90.57,70.23) R5.2 89.7,68.17 v1(89.7,55.8) ; R16.2 81,38.87 78.84,41.03 78.84,46.94 v1(79.54,47.64)
  BOTTOM w0.191: v1(79.54,47.64) 87.7,55.8 v1(89.7,55.8) ; J500.B36 v1(98.72,84.6) ; R30.2 12.44,50.6 12.44,53.41 15.72,56.69 15.72,58.9 16.95,60.14 16.95,61.31 23.33,67.69 88.03,67.69 v1(90.57,70.23)
SCP_MISO_1V8: length 42.5
  TOP w0.191: U8.U3 v1(19.53,22.07)
  BOTTOM w0.191: U10.4 9.8,51.58 9.37,51.16 R31.2 10.94,50.17 12.57,48.53 12.57,46.03 11.55,45.02 11.55,23.56 13.68,21.44 18.9,21.44 v1(19.53,22.07)
SCP_MOSI: length 151.1
  TOP w0.191: U7.57 77.78,25.1 75.9,26.98 75.9,48.82 75,49.72 59.25,49.72 54.73,54.24 35.79,54.24 33.32,51.77 28.17,51.77 27.86,51.47 27.86,50.11 v1(27.64,49.89) 27.05,50.47 27.05,52.18 28.17,53.3 30.88,53.3 35.27,57.68 54.04,57.68 58,61.65 58,72.1 57.44,72.65 57.44,85.05 57.25,85.24 55.16,85.24 54.9,84.98 54.9,83.8 54.44,83.33 v1(54.27,83.33)
  BOTTOM w0.191: R28.2 28.91,50.32 28.47,49.89 v1(27.64,49.89) 27.64,50.05 27.54,50.14 27.54,50.99 27.31,51.22 U9.6 ; J500.C02 v1(54.27,83.33)
SCP_MOSI_1V8: length 34.9
  TOP w0.191: U8.T3 v1(19.53,23.34)
  BOTTOM w0.191: v1(19.53,23.34) 19.53,23.37 18.93,23.98 15.42,23.98 14.07,25.32 14.07,44.02 17.19,47.14 17.19,48.2 R24.1
V_OFFSET: length 47.7
  TOP w0.254: U7.28 v1(88.65,36.67) ; v1(88.71,20.04) 88.65,20.09 U7.73 ; U7.33 86.15,33.76 v1(86.26,33.66) ; U7.63 v1(83.66,20.11) ; U7.68 v1(86.15,23.1) ; U7.38 83.66,33.91 v1(83.9,33.66) ; v1(91.49,36.64) 91.15,36.3 U7.23 ; U7.78 v1(91.15,23.21) ; U7.49 v1(78.08,29.1)
  TOP w0.508: TP24.1 104.78,38.07 ; TP24.1 100.75,38.07 100.35,37.68 99.74,37.68 v1(99.33,37.27) 98.75,36.69 D1.2 ; TP24.1 103.99,38.86 ; R12.2 v1(110.08,38.96) ; R54.1 122.74,39.5 122.71,39.47 120.88,39.47 117.71,36.3 116.69,36.3 v1(116.56,36.17) ; R51.2 v1(115.42,33.5)
  TOP w0.635: v1(97.26,34.65) 97.77,35.16 D1.2
  10_SIG4 w0.508: TP24.1 103.99,38.86 ; TP24.1 103.2,38.07 ; TP24.1 103.99,37.29 ; TP24.1 104.78,38.07
  BOTTOM w0.508: v1(83.66,20.11) 83.67,20.1 C13.2 ; C15.2 78.22,29.24 v1(78.08,29.1) ; v1(97.26,34.65) 98.25,35.64 C16.2 ; C14.2 89.38,19.36 v1(88.71,20.04)
VADJ: length 3.6
  BOTTOM w0.508: J500.F40 v1(103.8,78.25) ; J500.H40 v1(103.8,75.71) ; J500.E39 v1(102.53,80.79) ; J500.G39 v1(102.53,76.98)
VBIAS: length 43.9
  TOP w0.254: U7.30 v1(87.65,33.7) 87.55,33.8 87.26,33.8 87.16,33.9 U7.31 ; v1(92.61,20.02) 92.42,20.02 92.15,20.28 U7.80 ; U7.70 87.16,20.33 v1(87.4,20.09) 87.4,20.34 87.65,20.59 U7.71 ; U7.21 92.15,35.47 92.33,35.65 v1(93.04,35.65) ; v1(82.73,33.61) 82.65,33.69 U7.40 ; v1(82.02,18.65) 82.15,18.78 82.15,20.56 82.65,21.06 U7.61 ; U7.9 v1(92.71,27.6)
  TOP w0.381: R49.2 117.32,32.92 116.28,33.96 116.28,34.87 114.66,36.5 112.75,36.5 v1(111.56,37.69)
  TOP w0.635: D3.C 96.53,17.16 TP26.1
  BOTTOM w0.381: C27.2 82.55,35.97 ; C27.2 83.24,35.41 ; C27.2 82.55,34.85 ; TP26.1 97.16,16.99 ; TP26.1 96.37,17.78 ; TP26.1 96.37,16.21 ; TP26.1 95.58,16.99 ; C25.2 87.91,18.55 ; C25.2 86.79,18.55 ; C25.2 87.35,17.86 ; C25.2 87.35,20.04 v1(87.4,20.09) ; 87.28,35.41 C28.2 ; C28.2 87.96,35.97 ; C28.2 87.96,34.01 v1(87.65,33.7) ; C26.2 91.52,21.62 ; C26.2 90.83,21.06 ; C26.2 91.52,20.33 91.67,20.18 92.26,20.18 92.42,20.02 v1(92.61,20.02) ; C26.2 92.21,21.06
VIO_B_M2C: length 1.8
  BOTTOM w0.508: J500.J39 v1(102.53,74.44) ; J500.K40 v1(103.8,73.17)
VR_PG: length 5.2
  TOP w0.191: R43.2 119.29,2.81 D5.C 121.98,3.02 TP40.1
VR_PG_NEG: length 5.1
  TOP w0.191: R42.1 R43.1 119.23,4.68 117.45,6.46 U13.8
VREF_A_M2C: length 0.9
  BOTTOM w0.508: J500.H01 v1(53,75.71)
VREF_B_M2C: length 0.9
  BOTTOM w0.508: J500.K01 v1(53,73.17)
VRESET_DAD: length 15.7
  TOP w0.254: U7.13 95.52,29.6 95.86,29.95
  TOP w0.508: 110.42,32.39 R41.1 ; R41.1 111.53,32.39 ; R41.1 110.97,33.07 ; 111.05,34.62 C23.2 ; C23.2 112.17,34.62 ; C23.2 111.61,33.93 ; 104.43,34.77 D2.A ; D2.A 105.09,34.27 ; D2.A 105.09,35.28 ; D2.A 105.76,34.77 ; 109.25,32.11 C24.2 108.43,33.05 ; 110.26,34.62 C22.2 109.15,34.62 ; TP27.1 114.15,35.56 ; TP27.1 114.94,34.77 ; TP27.1 114.15,33.99 ; TP27.1 113.36,34.77 ; 107.8,33.93 C21.2 ; C21.2 107.24,34.62 ; C21.2 108.36,34.62
VRESET_EN: length 32.5
  TOP w0.254: v1(124.26,8.41) 122.77,8.41 U13.12
  TOP w0.508: 122.05,31.6 U15.3 ; U15.3 122.67,32.18 ; U15.3 122.67,31.02 ; U15.3 123.3,31.6 ; D7.2 127.48,28.83 ; D7.2 127.48,25.97 ; D7.2 126.16,27.4 ; R53.2 127.33,34.7 ; R53.2 126.65,34.14 ; R53.2 127.33,33.58 ; 123.55,37.24 R54.2 ; R54.2 124.11,37.92 ; R54.2 122.99,37.92 ; 118.67,31.75 R52.1 ; R52.1 119.23,32.44 ; R52.1 119.79,31.75 ; 126.65,30.96 R48.1 ; R48.1 127.33,30.4 ; R48.1 127.33,31.52
  BOTTOM w1.016: v1(124.26,8.41) 125,8.41 127.48,10.9 127.48,19.86 v1(124.69,22.66)
VRESET_EXT: length 41.2
  TOP w0.254: 120.86,7.74 121.49,7.11 122.76,7.11 U13.10
  TOP w0.508: C92.1 124.82,20.8 v1(125.07,20.55) ; C92.1 123.55,19.99 ; C92.1 123.55,21.62 ; TP41.1 110.34,3.81 ; TP41.1 110.34,2.24 ; TP41.1 111.13,3.02 ; C90.1 v1(112.88,4.93) ; v1(128.25,21.31) 127.48,22.07 127.48,23.09 ; 126.77,21.32 126.72,21.28 126.72,19.53 v1(125.33,19.53) ; v1(130.28,23.85) 129.39,24.74 129.39,30.48 R48.2 ; D7.1 128.8,23.1 ; D7.1 127.48,21.67 ; D7.1 127.48,23.09 ; R47.1 v1(128.91,3.96) ; v1(111.84,24.28) 111.61,24.51 R20.1 112.27,26.37 112.31,26.33 ; 127.48,23.09 129.39,23.09 v1(130.15,22.33) ; v1(126.72,6.32) 126.44,6.05 C91.1 ; R45.1 v1(111.99,2.39) ; R46.1 v1(114.78,3.66) ; 125.58,12.42 D6.A
  BOTTOM w0.508: C85.1 129.11,5.44 129.57,4.98 v1(130.84,4.98) ; TP41.1 111.36,3.02 v1(111.99,2.39)
  vias: v2(118.44,10.64) v2(118.44,9.69) v2(118.44,8.74) v2(118.44,7.79) v2(118.44,6.84) v2(119.39,10.64) v2(119.39,9.69) v2(119.39,8.74) v2(119.39,7.79) v2(119.39,6.84) v2(120.34,10.64) v2(120.34,9.69) v2(120.34,8.74) v2(120.34,7.79) v2(120.34,6.84) v2(121.29,10.64) v2(121.29,9.69) v2(121.29,8.74) v2(121.29,7.79) v2(121.29,6.84)
VRESET_RAIL: length 48.4
  TOP w0.254: U7.66 85.15,23.04 ; 85.15,23.04 85.13,23.01 84.79,23.01 84.65,22.88 U7.65 ; 85.15,23.04 85.15,26.1 v1(85.5,26.45) ; U7.36 84.65,33.74 84.76,33.63 85.15,33.63 ; 90.16,23.04 89.77,23.04 89.65,22.93 U7.75 ; 90.16,23.04 90.16,25.6 v1(89.31,26.45) ; 90.16,23.04 U7.76 ; 89.65,33.76 89.68,33.78 90.02,33.78 90.16,33.92 U7.25 ; 89.65,33.76 89.65,30.6 v1(89.31,30.26) ; 89.65,33.76 U7.26 ; 85.15,33.63 U7.35 ; 85.15,33.63 85.15,30.6 v1(85.5,30.26)
  TOP w0.508: 111.05,27.94 R20.2 ; R20.2 111.2,27.53 TP25.1 ; R20.2 111.61,28.63 ; R20.2 110.97,28.58 R41.2 ; 107.42,26.75 TP25.1 ; TP25.1 107.42,28.32 ; TP25.1 106.63,27.53 ; 87.4,25.52 v1(87.4,28.35) ; v1(87.4,28.35) 87.4,31.19 ; v1(87.4,28.35) 90.24,28.35
  10_SIG4 w0.508: 106.63,27.53 TP25.1 107.42,28.32
  vias: v1(85.5,28.35) v1(87.4,30.26) v1(87.4,26.45) v1(89.31,28.35)
N16506021: length 66.2
  TOP w0.191: U8.W18 v1(39.85,19.53)
  03_SIG1 w0.133: v1(39.85,19.53) 39.25,20.14 16.49,20.14 14.56,22.07 14.56,41.45 12.23,43.78 12.23,53.58 11.23,54.58 11.23,56.26 TP30.1
  BOTTOM w0.191: R21.2 10.49,56.67 TP30.1
N16506047: length 43.2
  TOP w0.191: U8.G3 v1(19.53,36.04)
  05_SIG2 w0.133: TP33.1 9.47,6.93 9.47,11.09 10.41,12.03 10.41,31.7 11.62,32.91 19.75,32.91 20.12,33.29 20.12,35.45 v1(19.53,36.04)
N16506207: length 24.3
  TOP w0.191: U8.D17 v1(38.58,39.85)
  08_SIG3 w0.133: v1(38.58,39.85) 39.2,40.47 47.85,40.47 48.13,40.74 48.13,44.71 50.89,47.47 50.89,52.29 TP32.1
N16506209: length 16.8
  TOP w0.191: U8.X17 v1(38.58,18.26)
  BOTTOM w0.191: v1(38.58,18.26) 37.95,17.63 37.95,12.1 35.66,9.81 35.66,4.43 TP31.1
N16506211: length 30.5
  TOP w0.191: U8.K4 v1(20.8,32.23)
  BOTTOM w0.191: TP29.1 23.6,11.66 22.71,12.55 22.71,21.2 22.27,21.65 22.27,30.77 v1(20.8,32.23)
N16506213: length 24.9
  TOP w0.191: U8.P4 v1(20.8,25.88)
  BOTTOM w0.191: v1(20.8,25.88) 21.44,25.25 21.44,13.69 17.73,9.98 17.73,5.66 TP28.1
N16506277: length 31.4
  TOP w0.191: U8.H3 v1(19.53,34.77)
  05_SIG2 w0.133: TP34.1 14.2,55.35 12.27,53.42 12.27,37.81 16.01,34.07 18.83,34.07 v1(19.53,34.77)
N16506279: length 29
  TOP w0.191: U8.G2 v1(18.26,36.04)
  05_SIG2 w0.133: TP35.1 14.76,56.21 14.76,54.13 13.82,53.19 13.82,51.31 14.28,50.85 14.28,47.29 13.18,46.2 13.18,38.48 16.15,35.51 17.68,35.51 18.21,36.04 v1(18.26,36.04)
N16506281: length 34.7
  TOP w0.191: U8.F3 v1(19.53,37.31)
  05_SIG2 w0.133: TP36.1 16.61,60.1 17.78,58.93 17.78,57.61 16.41,56.24 16.41,53.49 15.42,52.5 15.42,49.48 15.8,49.1 15.8,47.27 13.9,45.36 13.9,39.1 16.39,36.61 18.78,36.61 19.48,37.31 v1(19.53,37.31)
N16551414: length 12
  TOP w0.254: 96.29,27.1 U7.8
  TOP w0.508: 96.29,27.1 96.5,26.9 96.5,24.69 97.34,23.85 ; 99.35,20.17 D3.A ; D3.A 100.01,20.67 ; D3.A 100.01,19.66 ; D3.A 100.68,20.17 ; L6.1 105.26,21.67 ; L6.1 104.08,20.94 ; L6.1 105.26,20.21 ; L6.1 106.44,20.94
N16555452: length 1.1
  TOP w0.254: U7.10 95.19,28.1
N16558116: length 1.2
  TOP w0.254: 95.3,29.1 U7.12
N16559232: length 5.9
  TOP w0.191: v1(78.29,30.46) 78.29,30.31 78.49,30.1 U7.47
  BOTTOM w0.191: C19.2 78.42,30.33 v1(78.29,30.46) 77.03,30.46 C20.2
N16562882: length 4.4
  TOP w0.191: U7.45 78.64,31.1 v1(78.21,31.53)
  BOTTOM w0.191: R17.2 79.38,31.53 v1(78.21,31.53)
N16562886: length 7.8
  TOP w0.191: U7.44 79.18,31.6 78.16,32.62 78.16,35.97 R18.2
N16780951: length 5.9
  BOTTOM w0.191: TP3.1 115.48,23.02 U2.1 114.34,25.59 R6.1
N16783652: length 6.1
  TOP w0.191: R16.1 81,36.81 79.43,35.24 79.43,33.04 79.87,32.6 U7.42
N16819402: length 12.4
  TOP w0.191: R19.1 80.8,20.62 79.97,21.45 v1(78.95,21.45) ; v1(78.46,26.88) 78.74,26.6 U7.54
  BOTTOM w0.191: v1(78.46,26.88) 78.46,26.83 78.03,26.4 78.03,22.36 v1(78.95,21.45)
N16824071: length 3.5
  BOTTOM w0.191: R8.1 R9.2 119.07,37.12 118.56,37.62 U1.2
N16824656: length 4.1
  BOTTOM w0.191: TP2.1 117.32,36.84 U1.3 117.81,36.97 119.07,35.72 R7.2
N16836860: length 6.1
  TOP w0.191: R12.1 105.39,38.96 104.68,39.67 104.68,40.33 R13.1 104.31,40.69 U3.1
N16836862: length 6.5
  TOP w0.191: R14.1 108.89,40.81 108.89,41.81 108.59,42.11 108.59,43 ; 108.59,43 108.59,43 109,43.41 U4.2 ; 108.59,43 108.17,43.41 106.32,43.41 U3.2
N16841509: length 3.3
  BOTTOM w0.191: R10.2 124.1,46.36 U6.3
N16842070: length 6
  BOTTOM w0.191: U14.2 128.75,42.63 127.5,41.37 U5.1 125.78,40.21 R15.1
N16883881: length 3
  TOP w0.107: R34.2 96.01,10.01 96.52,9.5 97.82,9.5 98.02,9.7 U11.2
N16883883: length 153.5
  TOP w0.191: U11.6 104.72,9.05 v1(105.64,8.13)
  03_SIG1 w0.133: TP37.1 18.64,57 13.64,57 12.78,57.86 10.45,57.86 8.94,56.35 8.94,45.58 13.51,41.02 13.51,17.46 22.22,8.74 65.31,8.74 66.98,7.06 87.61,7.06 88.25,7.7 105.21,7.7 v1(105.64,8.13)
N16883884: length 3.1
  TOP w0.107: R35.2 96,8.74 96.52,9.26 97.84,9.26 98.05,9.05 U11.3
N16883892: length 10.7
  TOP w0.191: U11.4 97.68,8.4 96.17,6.88 94.52,6.88 92.56,4.93 TP38.1
N16884055: length 2.6
  BOTTOM w0.191: U9.13 22.43,52.22 21.41,53.24 R22.2
N16884056: length 2.2
  BOTTOM w0.191: R23.2 21.99,51.97 22.24,51.72 U9.12
N16884057: length 2.3
  BOTTOM w0.191: R24.2 21.99,50.7 22.51,51.22 U9.11
N16884058: length 3.1
  BOTTOM w0.191: R25.2 21.31,49.48 22.91,49.48 23.32,49.89 U9.10
N16884072: length 2.1
  BOTTOM w0.191: R30.1 14.59,50.03 14.59,50.8 13.81,51.58 U10.3
N16949503: length 2.9
  TOP w0.191: U13.3 116.96,9.71 114.36,9.71 C79.2
N16949620: length 9
  TOP w0.191: R47.2 126.21,3.02 v1(124.31,4.93) 124.31,5.56 123.41,6.46 U13.9
  BOTTOM w0.191: R44.2 125.43,4.93 v1(124.31,4.93) 123.19,4.93 C89.1
N16949632: length 6.2
  TOP w0.191: R45.2 115.67,3.12 115.67,6.83 115.95,7.11 116.96,7.11 U13.7
N16949636: length 4.7
  TOP w0.191: U13.4 116.96,9.06 115.62,9.06 114.28,7.72 112.98,7.72 C90.2
N16949644: length 2.9
  TOP w0.191: R46.2 115.17,6.73 115.17,6.96 115.97,7.76 116.96,7.76 U13.6
N16949726: length 2.9
  TOP w0.191: C91.2 125.44,7.76 122.77,7.76 U13.11
N16949871: length 4.7
  TOP w0.191: U16.1 117.32,27.74 R49.1 R51.1
N16949907: length 8.1
  TOP w0.191: U15.1 123.49,30.65 123.04,30.2 R50.1 121.01,27.94 U16.3
N16950963: length 5.5
  BOTTOM w0.191: U14.4 128.1,46.78 127.82,47.07 126.47,47.07 125.45,46.05 125.45,44.76 U6.1
N16971448: length 5.8
  BOTTOM w0.191: R56.2 R55.1 107.16,22.23 107.16,19.87

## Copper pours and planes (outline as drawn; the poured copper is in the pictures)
GND on BOTTOM (solid shape): outline of 169 points within 120.96,22.61 130.79,34.96
GND on TOP: 34.33,52.17 34.33,50.33 34.37,50.29 46.92,50.29 47.09,50.46 47.09,52.41 46.79,52.71 34.87,52.71
GND on TOP: 114.77,13.36 117.53,13.36 117.69,13.51 117.69,14.33 118.26,14.91 124.26,14.91 124.82,15.47 126.09,15.47 127.1,14.45 130.95,14.45 131.14,14.65 131.14,17.33 130.72,17.75 125.45,17.75 124.69,18.52 124.69,18.72 124.16,19.25 122.94,19.25 122.04,20.14 122.04,21.5 121.23,22.31 115.13,22.31 114.56,21.74 114.56,13.57
GND on TOP: 28.37,51.5 32.19,51.5 32.48,51.21 32.48,50.4 32.29,50.21 28.36,50.21 28.19,50.39 28.19,51.32
GND on TOP: 8.55,8.26 8.55,7.11 8.98,6.68 62.55,6.68 62.8,6.93 62.8,8.25 62.58,8.48 8.77,8.48
GND on TOP: 102.44,29.19 103,29.19 103,29.19 104.78,29.19 105.47,28.5 105.47,27.36 105.22,27.12 104.77,27.12 104.53,27.36 102.35,27.36 102.23,27.47 102.23,28.99
GND on TOP: 96.78,42.98 97.65,42.98 97.66,42.98 99.16,42.98 99.86,42.28 99.86,40.64 98.95,39.73 96.61,39.73 96.47,39.86 96.47,42.68
GND on TOP: 11.07,52.76 21.5,52.76 22.05,52.2 22.05,50.61 21.86,50.42 14.83,50.42 14.67,50.58 10.36,50.58 10.16,50.78 10.16,51.85
GND on TOP, BOTTOM, 03_SIG1, 05_SIG2, 08_SIG3, 10_SIG4: 131.69,1.89 131.69,3.79 132.32,3.79 132.32,1.89
GND on TOP, BOTTOM, 03_SIG1, 05_SIG2, 08_SIG3, 10_SIG4: 0.69,0.69 0.69,49.71 20.28,69.31 47.97,69.31 47.97,87.73 48.04,87.73 108.83,87.73 108.83,69.31 132.32,69.31 132.32,3.72 131.69,3.72 131.69,68.68 108.19,68.68 108.19,87.09 48.61,87.09 48.61,68.68 20.55,68.68 1.32,49.45 1.32,1.32 131.69,1.32 131.69,1.94 132.32,1.94 132.32,0.69
GND on BOTTOM: 117.83,14.68 124.55,14.68 124.77,14.9 124.77,18.77 124.01,19.53 118.09,19.53 117.41,18.85 117.41,15.1
GND on 02_GND1, 04_GND2: 0.64,0.64 0.64,49.73 20.26,69.36 47.92,69.36 47.92,87.78 108.88,87.78 108.88,69.36 132.37,69.36 132.37,0.64
GND on 09_GND3: 0.64,0.64 0.64,49.73 20.26,69.36 47.92,69.36 47.92,87.73 108.88,87.73 108.88,69.36 132.37,69.36 132.37,0.64
GND on 11_GND4: 0.64,0.64 0.64,49.73 20.26,69.36 47.92,69.36 47.92,87.75 108.88,87.75 108.88,69.36 132.37,69.36 132.37,0.64
P1V8 on TOP: 16.76,9.01 8.71,9.01 8.46,9.26 8.46,10.23 8.8,10.57 16.56,10.57 16.98,10.15 16.98,9.23
P1V8 on TOP: 30.65,49.7 34.35,49.7 34.45,49.8 40.92,49.8 40.96,49.76 40.96,47.96 40.56,47.55 30.78,47.55 30.49,47.84 30.49,49.54
P1V8 on TOP: 22.96,10.06 22.96,9 22.99,8.97 49.1,8.97 49.37,9.24 49.37,9.91 48.77,10.51 23.42,10.51
P1V8 on TOP: 55.6,10.45 62.44,10.45 62.76,10.14 62.76,9.2 62.53,8.98 55.37,8.98 55.32,9.03 55.32,10.18
P1V8 on TOP: 14.01,50.1 11.2,50.1 11.04,49.94 11.04,48.04 11.24,47.84 13.83,47.84 14.11,48.13 14.11,50
P1V8 on 06_PWR1: 0.64,0.64 0.64,49.73 20.26,69.36 47.92,69.36 47.92,87.77 108.88,87.77 108.88,69.36 132.37,69.36 132.37,25.96 110.76,25.96 110.76,0.64
P3V3 on TOP: 101.78,64.91 103.89,64.91 104.44,65.47 104.44,66.94 104.2,67.18 101.78,67.18 101.37,66.77 101.37,65.32
P3V3 on TOP: 111.92,45.2 115.35,45.2 116.2,44.35 116.2,43.6 116.01,43.41 114.47,43.41 114.21,43.67 111.7,43.67 111.6,43.77 111.6,44.88
P3V3 on TOP: 105.74,64.91 108.16,64.91 108.55,65.31 108.55,66.93 108.3,67.18 105.74,67.18 105.33,66.77 105.33,65.32
P3V3 on BOTTOM: 13.13,52.66 14.86,52.66 15.24,52.28 16.17,52.28 18.77,54.88 18.77,55.42 19.1,55.75 22.7,55.75 23.59,54.86 24.78,54.86 25.13,54.51 25.13,53.69 25.4,53.41 26.24,53.41 26.34,53.31 26.34,52.62 26.42,52.54 27.73,52.54 28.57,53.39 29.22,53.39 29.51,53.67 29.51,54.8 29.64,54.94 31.73,54.94 32.21,54.46 45.06,54.46 53.43,62.82 62.35,62.82 67.42,57.75 91.72,57.75 106.57,42.9 115.67,42.9 116.31,43.54 116.31,49.02 108.49,56.84 108.49,66.12 107.52,67.09 94,67.09 93.58,66.68 90.09,66.68 89.87,66.9 23.27,66.9 19.02,62.65 19.02,58.92 14.56,54.46 14.56,53.82 13.95,53.21 13.16,53.21 13.1,53.15 13.1,52.69
P3V3 on 10_SIG4: 100.69,2.01 117.07,2.01 130.41,15.34 130.41,48.74 126.09,53.06 122.91,53.06 113.77,43.92 113.77,42.65 118.21,38.2 118.21,33.22 97.26,12.27 97.26,5.44
P12V on TOP: 121.98,8.84 125.71,8.84 126.49,8.05 130.38,8.05 131.09,8.76 131.09,12.57 130.58,13.08 127.41,13.08 127.15,12.83 127.15,11.7 126.41,10.96 124.99,10.96 123.98,9.96 121.98,9.96
P12V on 05_SIG2: 104.72,30.33 101.53,33.52 101.53,69.62 101.71,69.8 101.71,81.77 100.47,83.01 99.72,83.01 98.95,83.79 98.35,83.79 97.57,83.01 96.87,83.01 96.72,83.17 96.72,86.52 97.14,86.95 107.11,86.95 107.66,86.4 107.66,69.45 109.15,67.96 128.35,67.96 131.29,65.01 131.29,31.98 129.64,30.33
P12V on 08_SIG3: 124.94,12.55 124.94,10.64 126.85,8.74 130.66,8.74 131.29,9.37 131.29,37.69 127.99,41 100.61,41 95.21,35.6 82.59,35.6 80.24,33.25 80.24,23.98 83.42,20.8 116.69,20.8
VCC2 on TOP: 17.24,10.24 17.24,9.02 17.27,8.99 22.51,8.99 22.71,9.19 22.71,10.28 22.45,10.54 17.54,10.54
VCC2 on TOP: 49.82,10.45 54.82,10.45 55.09,10.18 55.09,9.16 54.91,8.98 49.65,8.98 49.56,9.07 49.56,10.2
VCC2 on TOP: 46.09,49.82 49.12,49.82 49.2,49.73 49.2,48.03 48.92,47.74 46.23,47.74 45.98,47.99 45.98,49.71
VCC2 on 07_PWR2: 0.64,0.64 0.64,49.73 20.26,69.36 47.92,69.36 47.92,87.53 108.88,87.53 108.88,69.36 132.37,69.36 132.37,0.64
VCC2_EN on TOP: 114.01,43.14 112.92,43.14 112.75,42.97 111.61,42.97 111.53,42.89 111.53,38.54 112.92,37.16 113.37,37.16 114.48,38.27 114.48,42.67
(no net) on BOTTOM: 120.96,34.17 120.96,23.34 121.68,22.61 129.6,22.61 130.79,23.81 130.79,34.12 129.95,34.96 121.75,34.96
P3P3V1 on TOP: 102.31,85.34 106.11,85.34 107.58,83.87 107.58,69.68 106.99,69.09 106.99,67.56 106.81,67.38 105.74,67.38 105.23,67.89 104.57,67.89 104.39,68.07 104.39,70.09 105.61,71.31 105.61,82.61 104.73,83.48 103.7,83.48 103.04,82.82 101.86,82.82 101.72,82.96 101.72,84.75
P3P3V2 on TOP: 92.42,69.84 94.89,69.84 95.12,69.61 95.12,67.49 95,67.37 92.45,67.37 92.26,67.57 92.26,69.68
P3P3V2 on BOTTOM: 92.42,69.84 94.89,69.84 95.12,69.61 95.12,67.49 95.04,67.4 93.77,67.4 93.24,67.94 92.48,67.94 92.26,68.17 92.26,69.68
P3P3V2 on 05_SIG2: 93.07,82.62 95.24,82.62 95.98,81.88 97.54,81.88 98.28,82.62 99.18,82.62 99.56,82.25 99.56,79.39 98.97,78.8 97.34,78.8 97,78.47 97,70.31 96.62,69.92 96.62,68.53 96.16,68.07 93.34,68.07 92.65,68.76 92.65,70.09 92.81,70.25 92.81,82.36
P3P3V3 on TOP: 96.57,69.84 98.86,69.84 99.09,69.61 99.09,67.49 99,67.4 96.54,67.4 96.39,67.55 96.39,69.66
P3P3V3 on BOTTOM: 96.57,69.84 98.86,69.84 99.09,69.61 99.09,67.49 99,67.4 97.74,67.4 97.2,67.94 96.57,67.94 96.39,68.11 96.39,69.66
P3P3V3 on 08_SIG3: 99.35,82.41 99.35,72.24 98.33,71.21 97.33,71.21 96.54,70.42 96.54,68.13 97.16,67.51 101.42,67.51 103.15,69.24 103.15,82.59 102.97,82.78 99.73,82.78
P3P3V4 on TOP: 101.51,67.64 101.77,67.38 102.92,67.38 103.09,67.55 103.09,70.15 104.89,71.94 104.89,81.88 104.37,82.4 102.96,82.4 101.88,81.32 101.88,72.68 100.4,71.2 100.4,68.04 100.51,67.93 101.45,67.93 101.51,67.87
V_OFFSET on TOP: 96.58,37.98 98.99,37.98 98.99,38.15 100.05,39.2 104.41,39.2 105.11,38.5 105.11,37.93 104.5,37.32 99.86,37.32 98.93,36.39 98.93,35.44 97.79,34.3 97.13,34.3 96.92,34.51 96.92,35.17 96.67,35.42 96.62,35.42 96.43,35.61 96.43,37.83
V_OFFSET on 10_SIG4: 82.78,19.41 83.8,19.41 84.18,19.79 84.18,20.55 84.69,21.06 85.45,21.06 86.84,19.66 88.88,19.66 89.51,20.29 89.51,20.93 91.42,22.83 91.42,23.47 89.26,25.63 82.27,25.63 81.26,26.64 81.26,29.95 84.43,33.12 116.31,33.12 117.58,34.39 117.58,37.19 115.04,39.73 108.82,39.73 108.06,38.97 102.72,38.97 101.32,37.57 82.65,37.57 77.19,32.11 77.19,24.99
VADJ on 10_SIG4: 102.03,81.39 104.53,81.39 105.1,80.82 105.1,76.08 104.39,75.37 103.68,75.37 102.69,76.36 102.05,76.36 101.75,76.66 101.75,81.11
VBIAS on BOTTOM: 81.89,18.01 82.4,18.01 82.78,18.39 82.78,20.42 83.42,21.06 84.49,21.06 86.7,18.84 86.7,17.76 87.93,17.76 87.99,17.82 87.99,20.68 90.4,20.68 91.42,19.66 93.96,19.66 94.85,18.77 94.85,16.61 95.86,15.6 96.75,15.6 97.77,16.61 97.77,27.3 105.71,35.25 110.85,35.25 111.95,36.34 111.95,38.11 111.6,38.46 103.14,38.46 98.31,33.63 96.24,33.63 93.45,36.42 92.56,36.42 90.78,34.65 88.87,34.65 88.66,34.86 88.66,36.74 88.27,37.13 82.72,37.13 81.93,36.33 81.93,33.98 83.29,32.61 83.29,23.62 80.75,21.08 80.75,19.15
VIO_B_M2C on 10_SIG4: 102.89,74.94 104.34,73.48 104.34,72.44 103.79,71.88 102.18,71.88 101.55,72.51 101.55,74.55 101.94,74.94
VRESET_DAD on TOP: 95.23,29.44 95.86,29.44 100.56,34.14 100.56,35.66 100.69,35.79 102.34,35.79 104.24,33.88 106.4,33.88 107.8,32.49 107.8,31.6 107.93,31.47 109.83,31.47 110.34,31.98 113.13,31.98 115.42,34.26 115.42,35.03 114.4,36.04 114.02,36.04 113.13,35.15 106.91,35.15 105.01,37.06 100.05,37.06 99.29,36.3 99.29,35.03 96.88,32.61 96.88,31.47 95.61,30.2 95.23,30.2 95.1,30.07 95.1,29.57
VRESET_EN on TOP: 123.46,34.94 124.06,35.53 125.83,35.53 126.09,35.28 126.09,29.82 124.56,28.3 124.56,25.63 123.93,24.99 123.93,22.45 124.18,22.2 125.07,22.2 125.45,22.58 125.45,24.36 126.21,25.12 127.74,25.12 128.74,26.12 128.74,28.79 127.87,29.66 127.87,37.43 126.66,38.64 122.97,38.64 118.37,34.04 118.37,31.1 118.54,30.93 123.26,30.93 123.46,31.13
VRESET_EXT on TOP: 111.21,26.89 112.34,26.89 112.62,26.62 112.62,24.15 112.41,23.93 111.32,23.93 111.07,24.18 111.07,26.75
VRESET_EXT on TOP: 121.82,10.22 123.63,10.22 124.18,10.77 124.18,10.9 124.83,11.54 126.18,11.54 126.28,11.63 126.28,14.36 126.03,14.61 124.51,14.61 123.73,13.82 118.34,13.82 118.34,11.58 118.16,11.4 118.16,6.24 118.17,6.23 121.56,6.23 121.57,6.24 121.57,9.98
VRESET_EXT on TOP: 126.29,24.32 126.29,22.06 125.97,21.74 122.9,21.74 122.72,21.56 122.72,19.96 122.84,19.84 124.58,19.84 125.92,18.5 125.92,18.24 125.94,18.23 127.51,18.23 127.52,18.24 127.52,20.82 127.69,20.99 128.43,20.99 129.41,21.96 130.44,21.96 130.67,22.19 130.67,24.22 130.42,24.47 126.43,24.47
VRESET_EXT on TOP: 113.25,6.57 110.34,6.57 109.54,5.77 109.54,2.69 110.25,1.99 113.86,1.99 113.87,2 113.87,3.06 114.16,3.34 114.98,3.34 115.2,3.56 115.2,5.25 115.17,5.29 113.56,5.29 113.32,5.53 113.32,6.5
VRESET_EXT on BOTTOM: 118.23,7.34 121.39,7.34 121.77,7.72 121.77,11.15 122.54,11.92 124.1,11.92 124.48,12.3 124.48,13.79 124.33,13.94 117.96,13.94 117.71,13.69 117.71,7.87
VRESET_EXT on 06_PWR1: 111.4,0.64 111.4,25.33 132.37,25.33 132.37,0.64
